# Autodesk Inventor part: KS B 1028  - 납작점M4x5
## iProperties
Created: 2009-02
Part Number: KS B 1028  - 납작점M4x5
Material: Steel, Mild
Description: 6각 소켓 머리 없는 멈춤 나사
Document SubType Name: Modeling
Standard: KS B 1028
Designer: KYOUNG IL JANG
Standards Organization: KS
Language: ko-KR
Size Designation: 납작점M4x5
Categories: <MemberInstance><Categories><Category DisplayName="조임쇠" InternalName="e4da775c-781d-43d5-af7c-5136215cf5a6" Mnemonic="FSTN"><Category DisplayName="볼트" InternalN
Density: 1 g/cm^3
IsCustomPart: 0
Author: KYOUNG IL JANG
